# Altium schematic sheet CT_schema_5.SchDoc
size 383 x 311 mm
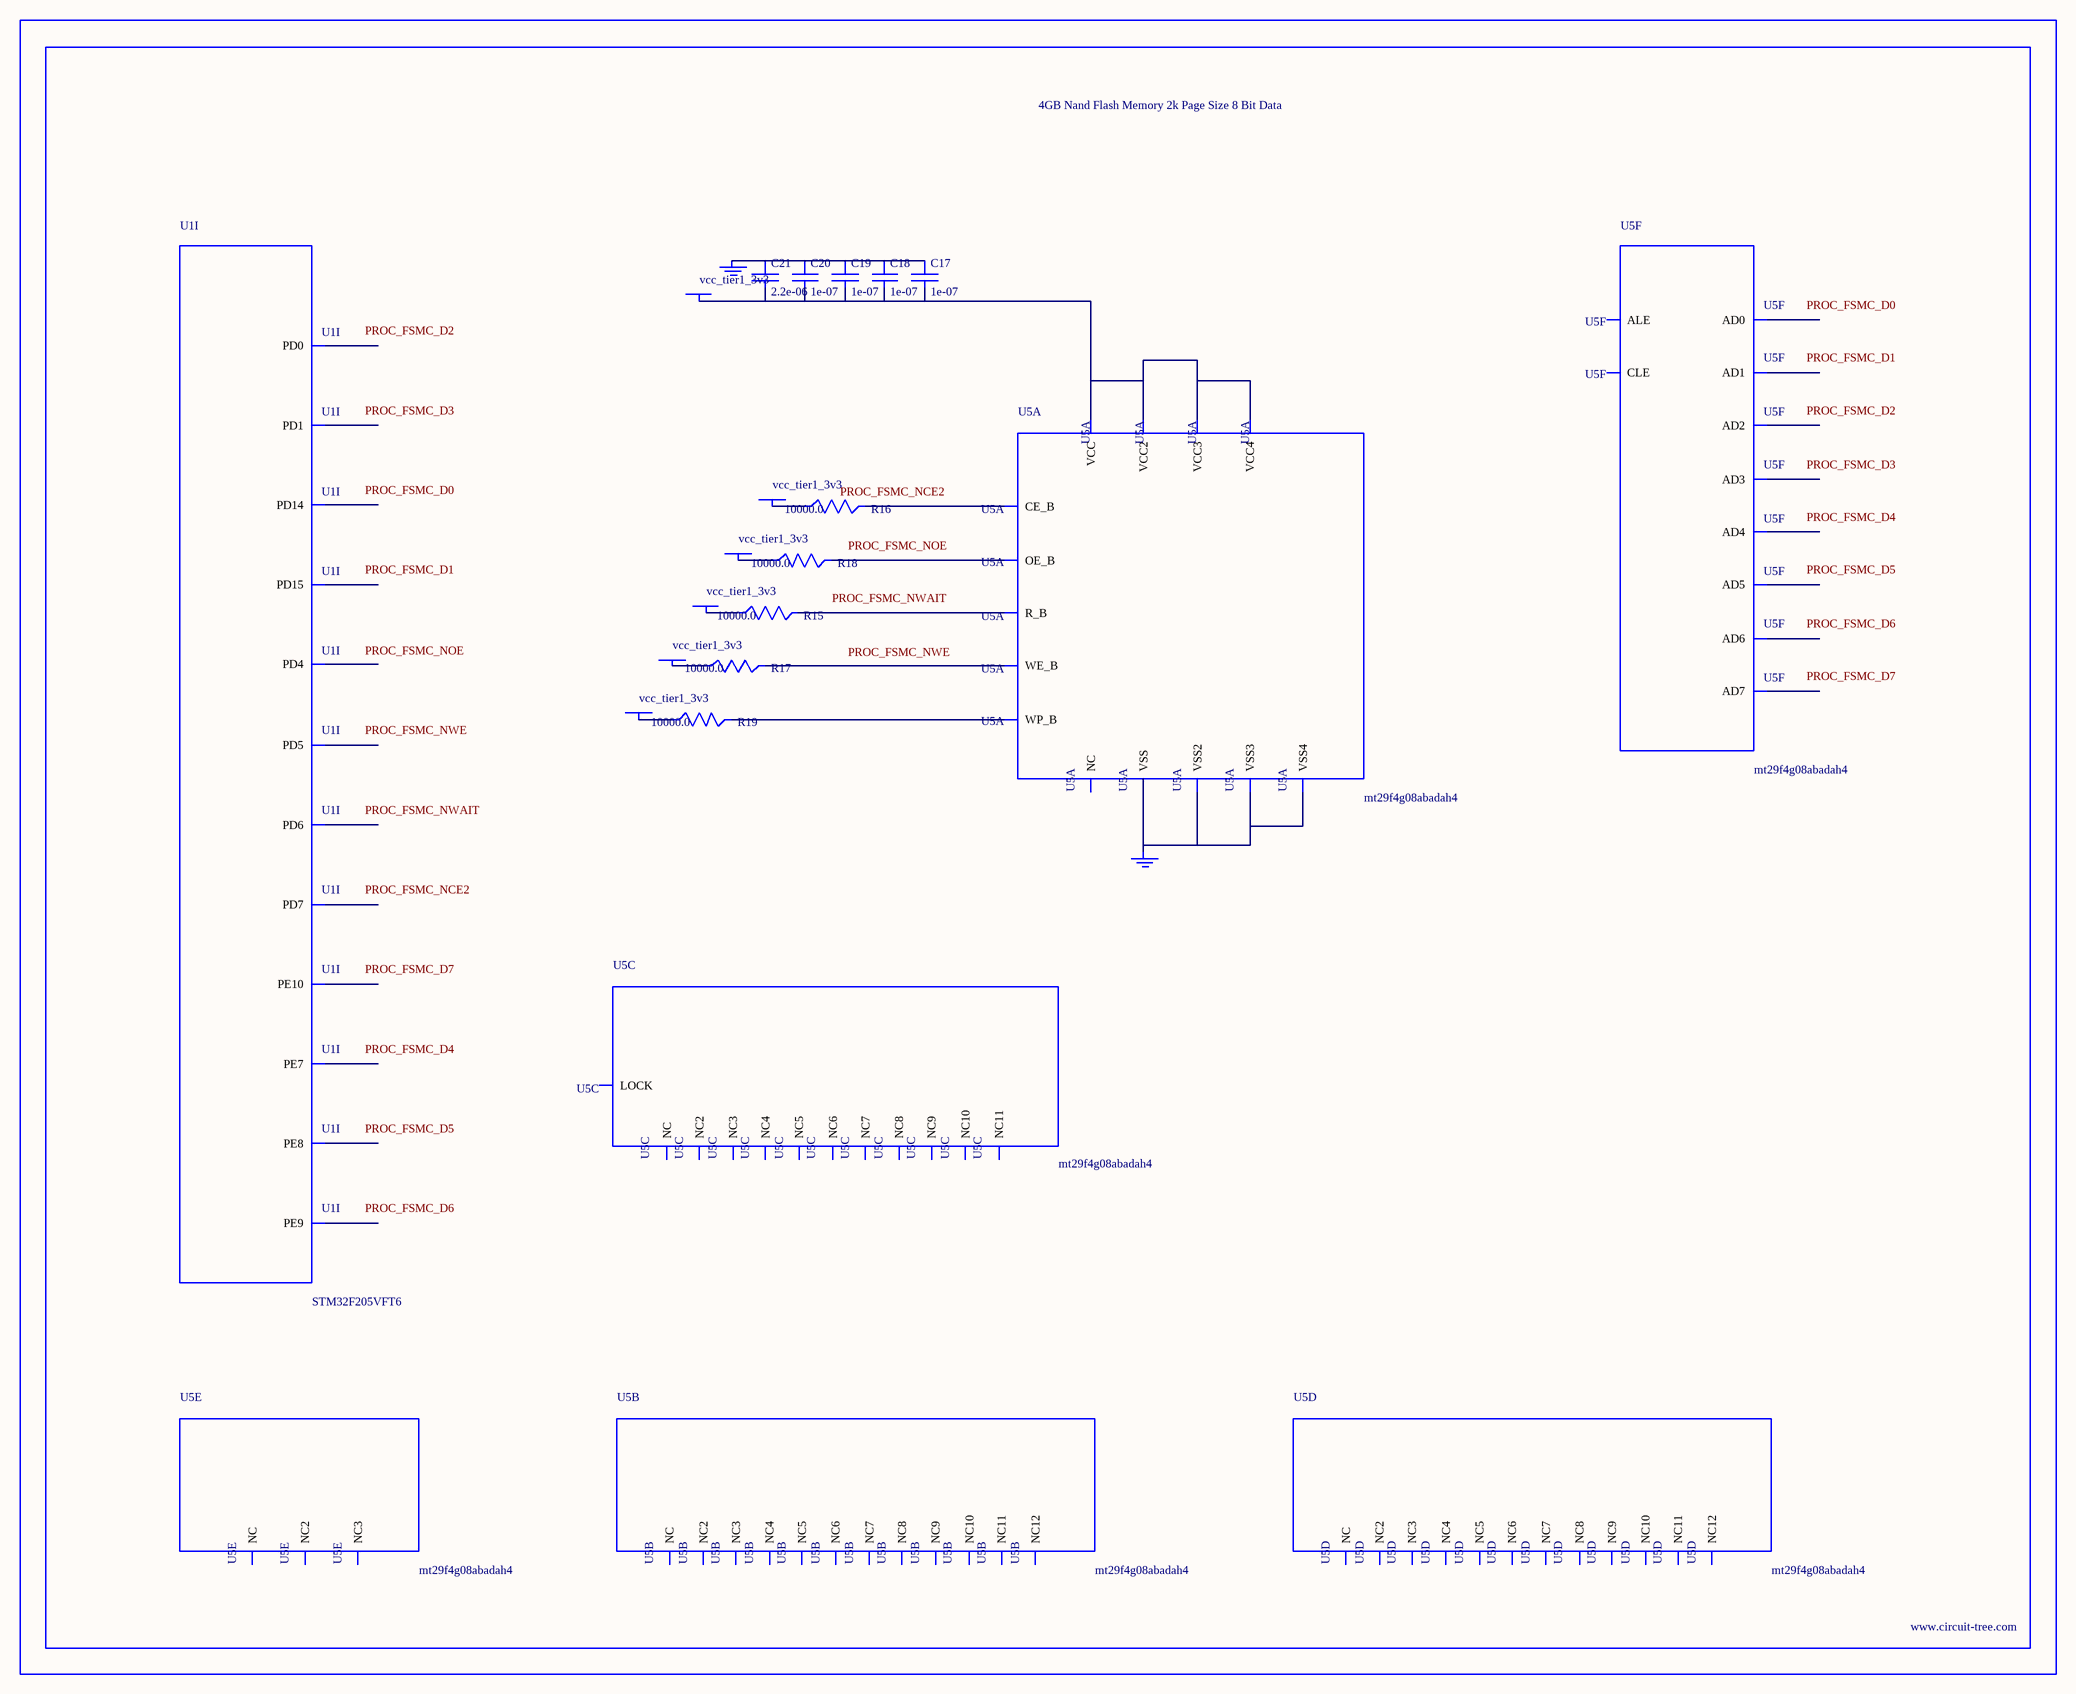
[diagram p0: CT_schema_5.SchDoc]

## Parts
BORDER4  (no value)
C17  1e-07  [C0402]
C18  1e-07  [C0402]
C19  1e-07  [C0402]
C20  1e-07  [C0402]
C21  2.2e-06  [C0603]
GND_INSTANCE_4_0  (no value)
GND_INSTANCE_4_1  (no value)
POWER_INSTANCE_4_0  vcc_tier1_3v3
POWER_INSTANCE_4_1  vcc_tier1_3v3
POWER_INSTANCE_4_2  vcc_tier1_3v3
POWER_INSTANCE_4_3  vcc_tier1_3v3
POWER_INSTANCE_4_4  vcc_tier1_3v3
POWER_INSTANCE_4_5  vcc_tier1_3v3
R15  10000.0  [R0603]
R16  10000.0  [R0603]
R17  10000.0  [R0603]
R18  10000.0  [R0603]
R19  10000.0  [R0603]
U1  STM32F205VFT6  [LQFP100]  (part I of 11)
U5  mt29f4g08abadah4  [VFBGA-63]  (parts A,B,C,D,E,F of 6)

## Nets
NetC17_1: C17.1 C18.1 C19.1 C20.1 C21.1 GND_INSTANCE_4_0.0(GND)
NetC17_2: C17.2 C18.2 C19.2 C20.2 C21.2 POWER_INSTANCE_4_0.0(PWR) U5.D3(VCC) U5.G4(VCC2) U5.H8(VCC3) U5.J6(VCC4)
NetGND_INSTANCE_4_1_0: GND_INSTANCE_4_1.0(GND) U5.C5(VSS) U5.F7(VSS2) U5.K3(VSS3) U5.K8(VSS4)
NetPOWER_INSTANCE_4_1_0: POWER_INSTANCE_4_1.0(PWR) R15.1
NetPOWER_INSTANCE_4_2_0: POWER_INSTANCE_4_2.0(PWR) R16.1
NetPOWER_INSTANCE_4_3_0: POWER_INSTANCE_4_3.0(PWR) R17.1
NetPOWER_INSTANCE_4_4_0: POWER_INSTANCE_4_4.0(PWR) R18.1
NetPOWER_INSTANCE_4_5_0: POWER_INSTANCE_4_5.0(PWR) R19.1
NetR15_2: R15.2 U5.C8(R_B)
NetR16_2: R16.2 U5.C6(CE_B)
NetR17_2: R17.2 U5.C7(WE_B)
NetR18_2: R18.2 U5.D4(OE_B)
NetR19_2: R19.2 U5.C3(WP_B)

Not connected (* = marked no-connect by the designer): U1 38(PE7) 39(PE8) 40(PE9) 41(PE10) 61(PD14) 62(PD15) 81(PD0) 82(PD1) 85(PD4) 86(PD5) 87(PD6) 88(PD7); U5 A1(NC) A2(NC3) A9(NC4) A10(NC2) B1(NC5) B9(NC7) B10(NC6) C4(ALE) D5(CLE) D6(NC8) D7(NC9) D8(NC10) E3(NC11) E4(NC12) E5(NC) E6(NC2) E7(NC3) E8(NC4) F3(NC5) F4(NC6) F5(NC7) F6(NC8) F8(NC9) G3(NC) G5(LOCK) G6(NC10) G7(NC11) G8(NC) H3(NC2) H4(AD0) H5(NC3) H6(NC4) H7(NC5) J3(NC6) J4(AD1) J5(NC7) J7(AD5) J8(AD7) K4(AD2) K5(AD3) K6(AD4) K7(AD6) L1(NC8) L2(NC10) L9(NC11) L10(NC9) M1(NC12) M2(NC2) M9(NC3) M10(NC)

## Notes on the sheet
- Labels drawn without touching a wire or pin: PROC_FSMC_D0, PROC_FSMC_D1, PROC_FSMC_D2, PROC_FSMC_D3, PROC_FSMC_D4, PROC_FSMC_D5, PROC_FSMC_D6, PROC_FSMC_D7, PROC_FSMC_NCE2, PROC_FSMC_NOE, PROC_FSMC_NWAIT, PROC_FSMC_NWE

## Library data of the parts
BORDER4 = BORDER_PAGE4
C17-C20 = C0402C104K3RACTU
C21 = C0603C225K8RACTU
GND_INSTANCE_4_0 GND_INSTANCE_4_1 = GND
POWER_INSTANCE_4_0-POWER_INSTANCE_4_5 = PWR
R15-R19 = RC0603JR-0710KL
